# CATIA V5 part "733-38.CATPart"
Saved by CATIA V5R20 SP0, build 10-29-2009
Part number: 733-38
Bounding box of the stored display mesh (mm): x -33 to 33, y -32.999 to 32.999, z -37 to 71
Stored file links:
  C:\Users\Utente\Desktop\IO LAVORO\3D X SITO CF\X SITO\733\733-38.CATPart
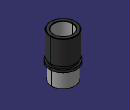
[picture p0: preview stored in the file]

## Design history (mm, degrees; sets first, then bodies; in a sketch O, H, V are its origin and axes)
Set1
  DatumSurface1 to DatumSurface25 "733-38"
Body1 (main body)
